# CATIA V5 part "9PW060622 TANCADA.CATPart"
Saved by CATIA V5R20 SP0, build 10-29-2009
Part number: 9PW060622 TANCADA
Revision: ANY
Definition: UNKNOWN
Nomenclature: 9PW060622 TANCADA
Source: Unknown
Bounding box of the stored display mesh (mm): x -124.996 to 0, y -5.5 to 3.5, z -3.1 to 3.1
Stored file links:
  C:\Users\Utente\Desktop\IO LAVORO\3D X SITO CF\CUMSA\3D files PW\pw060622\pw060622_injection\9PW060622 TANCADA.CATPart
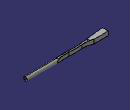
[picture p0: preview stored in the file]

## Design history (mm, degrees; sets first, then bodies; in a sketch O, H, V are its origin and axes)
Body1 "Chaflán1" (main body)
  Solid1: solid without history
